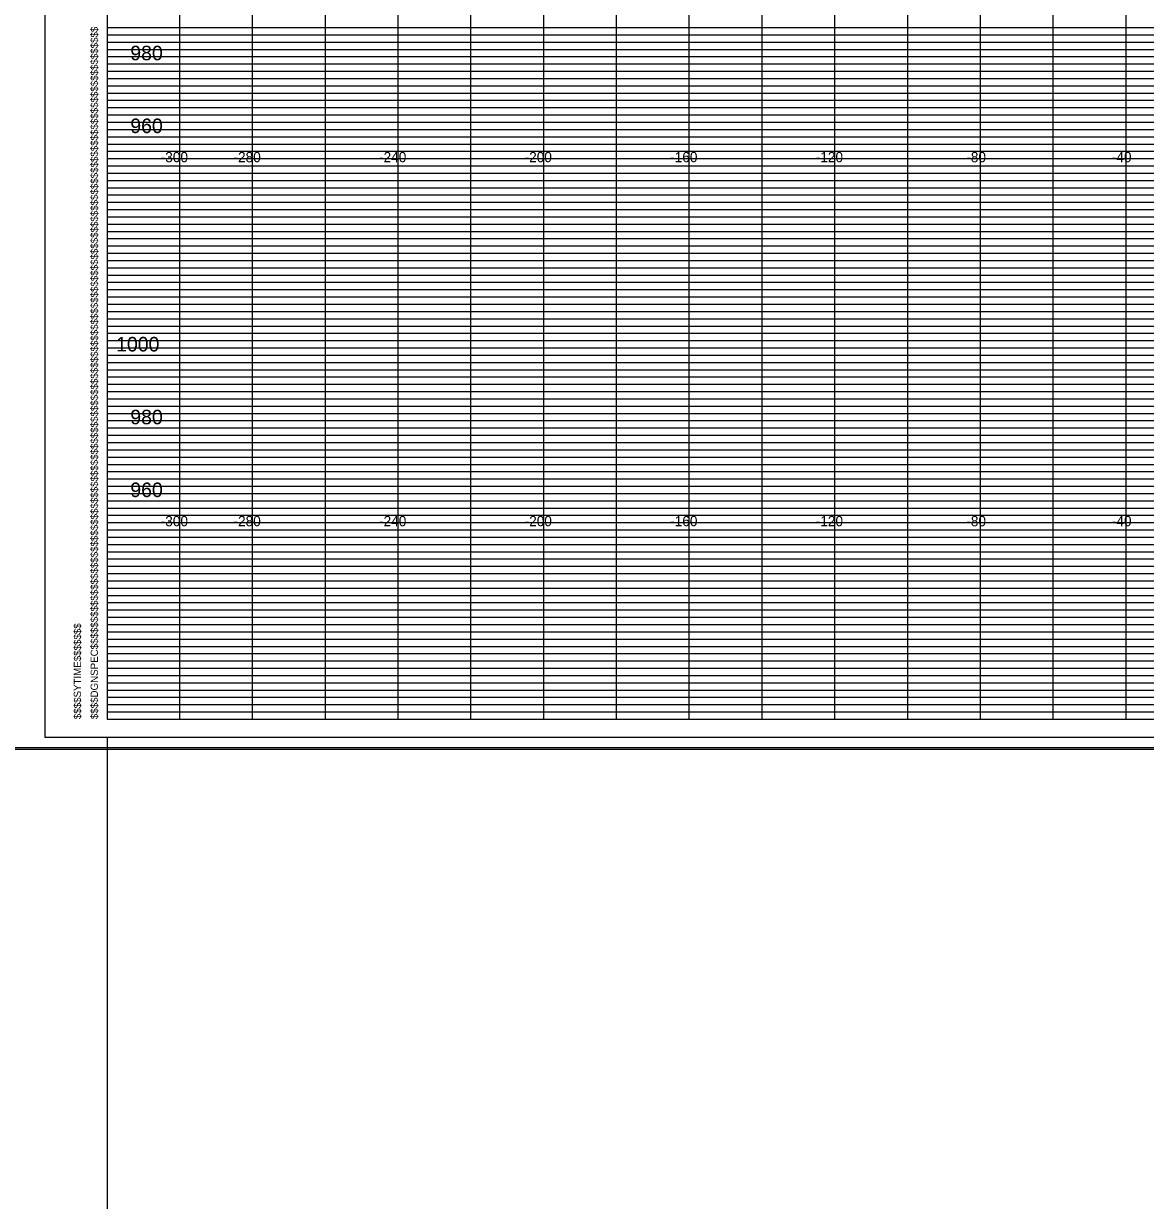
# Model space of a CAD drawing. Extents: x 2313580 to 2322968, y 282099 to 303247.
# Drawn here: x 2315275.9 to 2315584.2, y 287455.4 to 287778.8 of the extents above; entities that cross this region are included whole.
import ezdxf

# ---------------------------------------------------------------- set-up
doc = ezdxf.new("R2010")
doc.units = 0
for name, color, linetype in [('DESIGN - SCRATCH - User 1', 7, 'Continuous'), ('DESIGN - SHEET - Corner Text', 7, 'Continuous'), ('DESIGN - SHEET - Light Grid', 7, 'Continuous'), ('DESIGN - SHEET - Linework', 7, 'Continuous'), ('DESIGN - SHEET - Plot Shape', 7, 'Continuous'), ('DESIGN - TYPICAL - Text', 7, 'Continuous')]:
    doc.layers.add(name, color=color, linetype=linetype)

msp = doc.modelspace()

# ---------------------------------------------------------------- linework, layer by layer
at = {"layer": 'DESIGN - SCRATCH - User 1'}
msp.add_line((2315298.88, 287582.67), (2315298.88, 284487.81), dxfattribs=at)
at = {"layer": 'DESIGN - SHEET - Light Grid'}
for p, q in [((2315298.88, 287777.67), (2315458.88, 287777.67)), ((2315298.88, 287775.67), (2315458.88, 287775.67)), ((2315458.88, 287777.67), (2315618.88, 287777.67)), ((2315458.88, 287775.67), (2315618.88, 287775.67)), ((2315298.88, 287773.67), (2315458.88, 287773.67)), ((2315458.88, 287773.67), (2315618.88, 287773.67)), ((2315298.88, 287771.67), (2315458.88, 287771.67)), ((2315298.88, 287769.67), (2315458.88, 287769.67)), ((2315458.88, 287771.67), (2315618.88, 287771.67)), ((2315458.88, 287769.67), (2315618.88, 287769.67)), ((2315298.88, 287765.67), (2315458.88, 287765.67)), ((2315458.88, 287765.67), (2315618.88, 287765.67)), ((2315298.88, 287763.67), (2315458.88, 287763.67)), ((2315458.88, 287763.67), (2315618.88, 287763.67)), ((2315298.88, 287761.67), (2315458.88, 287761.67)), ((2315298.88, 287759.67), (2315458.88, 287759.67)), ((2315458.88, 287761.67), (2315618.88, 287761.67)), ((2315458.88, 287759.67), (2315618.88, 287759.67)), ((2315298.88, 287757.67), (2315458.88, 287757.67)), ((2315458.88, 287757.67), (2315618.88, 287757.67)), ((2315298.88, 287755.67), (2315458.88, 287755.67)), ((2315298.88, 287753.67), (2315458.88, 287753.67)), ((2315458.88, 287755.67), (2315618.88, 287755.67)), ((2315458.88, 287753.67), (2315618.88, 287753.67)), ((2315298.88, 287751.67), (2315458.88, 287751.67)), ((2315298.88, 287749.67), (2315458.88, 287749.67)), ((2315458.88, 287751.67), (2315618.88, 287751.67)), ((2315458.88, 287749.67), (2315618.88, 287749.67)), ((2315298.88, 287745.67), (2315458.88, 287745.67)), ((2315298.88, 287743.67), (2315458.88, 287743.67)), ((2315458.88, 287745.67), (2315618.88, 287745.67)), ((2315458.88, 287743.67), (2315618.88, 287743.67)), ((2315298.88, 287741.67), (2315458.88, 287741.67)), ((2315298.88, 287739.67), (2315458.88, 287739.67)), ((2315458.88, 287741.67), (2315618.88, 287741.67)), ((2315458.88, 287739.67), (2315618.88, 287739.67)), ((2315298.88, 287737.67), (2315458.88, 287737.67)), ((2315458.88, 287737.67), (2315618.88, 287737.67)), ((2315298.88, 287735.67), (2315458.88, 287735.67)), ((2315298.88, 287733.67), (2315458.88, 287733.67)), ((2315458.88, 287735.67), (2315618.88, 287735.67)), ((2315458.88, 287733.67), (2315618.88, 287733.67)), ((2315298.88, 287731.67), (2315458.88, 287731.67)), ((2315458.88, 287731.67), (2315618.88, 287731.67)), ((2315298.88, 287729.67), (2315458.88, 287729.67)), ((2315458.88, 287729.67), (2315618.88, 287729.67)), ((2315298.88, 287725.67), (2315458.88, 287725.67)), ((2315298.88, 287723.67), (2315458.88, 287723.67)), ((2315458.88, 287725.67), (2315618.88, 287725.67)), ((2315458.88, 287723.67), (2315618.88, 287723.67)), ((2315298.88, 287721.67), (2315458.88, 287721.67)), ((2315458.88, 287721.67), (2315618.88, 287721.67)), ((2315298.88, 287719.67), (2315458.88, 287719.67)), ((2315298.88, 287717.67), (2315458.88, 287717.67)), ((2315458.88, 287719.67), (2315618.88, 287719.67)), ((2315458.88, 287717.67), (2315618.88, 287717.67)), ((2315298.88, 287715.67), (2315458.88, 287715.67)), ((2315458.88, 287715.67), (2315618.88, 287715.67)), ((2315298.88, 287713.67), (2315458.88, 287713.67)), ((2315298.88, 287711.67), (2315458.88, 287711.67)), ((2315458.88, 287713.67), (2315618.88, 287713.67)), ((2315458.88, 287711.67), (2315618.88, 287711.67)), ((2315298.88, 287709.67), (2315458.88, 287709.67)), ((2315458.88, 287709.67), (2315618.88, 287709.67)), ((2315298.88, 287705.67), (2315458.88, 287705.67)), ((2315458.88, 287705.67), (2315618.88, 287705.67)), ((2315298.88, 287703.67), (2315458.88, 287703.67)), ((2315298.88, 287701.67), (2315458.88, 287701.67)), ((2315458.88, 287703.67), (2315618.88, 287703.67)), ((2315458.88, 287701.67), (2315618.88, 287701.67)), ((2315298.88, 287699.67), (2315458.88, 287699.67)), ((2315298.88, 287697.67), (2315458.88, 287697.67)), ((2315458.88, 287699.67), (2315618.88, 287699.67)), ((2315458.88, 287697.67), (2315618.88, 287697.67)), ((2315298.88, 287695.67), (2315458.88, 287695.67)), ((2315458.88, 287695.67), (2315618.88, 287695.67)), ((2315298.88, 287693.67), (2315458.88, 287693.67)), ((2315298.88, 287691.67), (2315458.88, 287691.67)), ((2315458.88, 287693.67), (2315618.88, 287693.67)), ((2315458.88, 287691.67), (2315618.88, 287691.67)), ((2315298.88, 287689.67), (2315458.88, 287689.67)), ((2315458.88, 287689.67), (2315618.88, 287689.67)), ((2315298.88, 287685.67), (2315458.88, 287685.67)), ((2315458.88, 287685.67), (2315618.88, 287685.67)), ((2315298.88, 287683.67), (2315458.88, 287683.67)), ((2315298.88, 287681.67), (2315458.88, 287681.67)), ((2315458.88, 287683.67), (2315618.88, 287683.67)), ((2315458.88, 287681.67), (2315618.88, 287681.67)), ((2315298.88, 287679.67), (2315458.88, 287679.67)), ((2315458.88, 287679.67), (2315618.88, 287679.67)), ((2315298.88, 287677.67), (2315458.88, 287677.67)), ((2315298.88, 287675.67), (2315458.88, 287675.67)), ((2315458.88, 287677.67), (2315618.88, 287677.67)), ((2315458.88, 287675.67), (2315618.88, 287675.67)), ((2315298.88, 287673.67), (2315458.88, 287673.67)), ((2315298.88, 287671.67), (2315458.88, 287671.67)), ((2315458.88, 287673.67), (2315618.88, 287673.67)), ((2315458.88, 287671.67), (2315618.88, 287671.67)), ((2315298.88, 287669.67), (2315458.88, 287669.67)), ((2315458.88, 287669.67), (2315618.88, 287669.67)), ((2315298.88, 287665.67), (2315458.88, 287665.67)), ((2315458.88, 287665.67), (2315618.88, 287665.67)), ((2315298.88, 287663.67), (2315458.88, 287663.67)), ((2315458.88, 287663.67), (2315618.88, 287663.67)), ((2315298.88, 287661.67), (2315458.88, 287661.67)), ((2315298.88, 287659.67), (2315458.88, 287659.67)), ((2315458.88, 287661.67), (2315618.88, 287661.67)), ((2315458.88, 287659.67), (2315618.88, 287659.67)), ((2315298.88, 287657.67), (2315458.88, 287657.67)), ((2315298.88, 287655.67), (2315458.88, 287655.67)), ((2315458.88, 287657.67), (2315618.88, 287657.67)), ((2315458.88, 287655.67), (2315618.88, 287655.67)), ((2315298.88, 287653.67), (2315458.88, 287653.67)), ((2315458.88, 287653.67), (2315618.88, 287653.67)), ((2315298.88, 287651.67), (2315458.88, 287651.67)), ((2315298.88, 287649.67), (2315458.88, 287649.67)), ((2315458.88, 287651.67), (2315618.88, 287651.67)), ((2315458.88, 287649.67), (2315618.88, 287649.67)), ((2315298.88, 287645.67), (2315458.88, 287645.67)), ((2315298.88, 287643.67), (2315458.88, 287643.67)), ((2315458.88, 287645.67), (2315618.88, 287645.67)), ((2315458.88, 287643.67), (2315618.88, 287643.67)), ((2315298.88, 287641.67), (2315458.88, 287641.67)), ((2315298.88, 287639.67), (2315458.88, 287639.67)), ((2315458.88, 287641.67), (2315618.88, 287641.67)), ((2315458.88, 287639.67), (2315618.88, 287639.67)), ((2315298.88, 287637.67), (2315458.88, 287637.67)), ((2315458.88, 287637.67), (2315618.88, 287637.67)), ((2315298.88, 287635.67), (2315458.88, 287635.67)), ((2315298.88, 287633.67), (2315458.88, 287633.67)), ((2315458.88, 287635.67), (2315618.88, 287635.67)), ((2315458.88, 287633.67), (2315618.88, 287633.67)), ((2315298.88, 287631.67), (2315458.88, 287631.67)), ((2315298.88, 287629.67), (2315458.88, 287629.67)), ((2315458.88, 287631.67), (2315618.88, 287631.67)), ((2315458.88, 287629.67), (2315618.88, 287629.67)), ((2315298.88, 287625.67), (2315458.88, 287625.67)), ((2315298.88, 287623.67), (2315458.88, 287623.67)), ((2315458.88, 287625.67), (2315618.88, 287625.67)), ((2315458.88, 287623.67), (2315618.88, 287623.67)), ((2315298.88, 287621.67), (2315458.88, 287621.67)), ((2315458.88, 287621.67), (2315618.88, 287621.67)), ((2315298.88, 287619.67), (2315458.88, 287619.67)), ((2315298.88, 287617.67), (2315458.88, 287617.67)), ((2315458.88, 287619.67), (2315618.88, 287619.67)), ((2315458.88, 287617.67), (2315618.88, 287617.67)), ((2315298.88, 287615.67), (2315458.88, 287615.67)), ((2315298.88, 287613.67), (2315458.88, 287613.67)), ((2315458.88, 287615.67), (2315618.88, 287615.67)), ((2315458.88, 287613.67), (2315618.88, 287613.67)), ((2315298.88, 287611.67), (2315458.88, 287611.67)), ((2315458.88, 287611.67), (2315618.88, 287611.67)), ((2315298.88, 287609.67), (2315458.88, 287609.67)), ((2315458.88, 287609.67), (2315618.88, 287609.67)), ((2315298.88, 287605.67), (2315458.88, 287605.67)), ((2315458.88, 287605.67), (2315618.88, 287605.67)), ((2315298.88, 287603.67), (2315458.88, 287603.67)), ((2315298.88, 287601.67), (2315458.88, 287601.67)), ((2315458.88, 287603.67), (2315618.88, 287603.67)), ((2315458.88, 287601.67), (2315618.88, 287601.67)), ((2315298.88, 287599.67), (2315458.88, 287599.67)), ((2315298.88, 287597.67), (2315458.88, 287597.67)), ((2315458.88, 287599.67), (2315618.88, 287599.67)), ((2315458.88, 287597.67), (2315618.88, 287597.67)), ((2315298.88, 287595.67), (2315458.88, 287595.67)), ((2315458.88, 287595.67), (2315618.88, 287595.67)), ((2315298.88, 287593.67), (2315458.88, 287593.67)), ((2315298.88, 287591.67), (2315458.88, 287591.67)), ((2315458.88, 287593.67), (2315618.88, 287593.67)), ((2315458.88, 287591.67), (2315618.88, 287591.67)), ((2315298.88, 287589.67), (2315458.88, 287589.67)), ((2315458.88, 287589.67), (2315618.88, 287589.67))]:
    msp.add_line(p, q, dxfattribs=at)
at = {"layer": 'DESIGN - SHEET - Linework'}
for p, q in [((2315318.88, 287587.67), (2315318.88, 288007.67)), ((2315338.88, 287587.67), (2315338.88, 288007.67)), ((2315358.88, 287587.67), (2315358.88, 288007.67)), ((2315378.88, 287587.67), (2315378.88, 288007.67)), ((2315398.88, 287587.67), (2315398.88, 288007.67)), ((2315418.88, 287587.67), (2315418.88, 288007.67)), ((2315438.88, 287587.67), (2315438.88, 288007.67)), ((2315458.88, 287587.67), (2315458.88, 288007.67)), ((2315478.88, 287587.67), (2315478.88, 288007.67)), ((2315498.88, 287587.67), (2315498.88, 288007.67)), ((2315518.88, 287587.67), (2315518.88, 288007.67)), ((2315538.88, 287587.67), (2315538.88, 288007.67)), ((2315558.88, 287587.67), (2315558.88, 288007.67)), ((2315578.88, 287587.67), (2315578.88, 288007.67)), ((2315298.88, 287767.67), (2315938.88, 287767.67)), ((2315298.88, 287747.67), (2315938.88, 287747.67)), ((2315298.88, 287727.67), (2315938.88, 287727.67)), ((2315298.88, 287707.67), (2315938.88, 287707.67)), ((2315298.88, 287687.67), (2315938.88, 287687.67)), ((2315298.88, 287667.67), (2315938.88, 287667.67)), ((2315298.88, 287647.67), (2315938.88, 287647.67)), ((2315298.88, 287627.67), (2315938.88, 287627.67)), ((2315298.88, 287607.67), (2315938.88, 287607.67)), ((2315262.42, 287579.39), (2315943.22, 287579.39))]:
    msp.add_line(p, q, dxfattribs=at)
msp.add_lwpolyline([(2315298.88, 288007.67), (2315298.88, 287587.67), (2315938.88, 287587.67), (2315938.88, 288007.67), (2315298.88, 288007.67)], dxfattribs=at)
at = {"layer": 'DESIGN - SHEET - Plot Shape'}
for points in [[(2315262.82, 288015.55), (2315942.82, 288015.55), (2315942.82, 287579.79), (2315262.82, 287579.79)], [(2315281.88, 288007.67), (2315938.88, 288007.67), (2315938.88, 287582.67), (2315281.88, 287582.67)]]:
    msp.add_lwpolyline(points, close=True, dxfattribs=at)

# ---------------------------------------------------------------- texts
at = {"layer": 'DESIGN - SHEET - Corner Text'}
for s, height, p in [('$$$$DGNSPEC$$$$$$$$$$$$$$$$$$$$$$$$$$$$$$$$$$$$$$$$$$$$$$$$$$$$$$$$$$$$$$$$$$$$$$$$$$$$$$$$$$$$$$$$$$$$$$$$$$$$$$$$$$$$$$$$$$$', 2.00004, (2315296.36, 287587.67)), ('$$$$SYTIME$$$$$$$', 2, (2315291.72, 287587.67))]:
    msp.add_text(s, height=height, rotation=90, dxfattribs=at).set_placement(p)
at = {"layer": 'DESIGN - SHEET - Linework'}
for p in [(2315318.88, 287747.67), (2315318.88, 287647.67)]:
    msp.add_text('-', height=0.0001, dxfattribs=at).set_placement(p)
at = {"layer": 'DESIGN - TYPICAL - Text'}
for s, height, p in [('980', 4, (2315305.26, 287768.67)), ('960', 4, (2315305.26, 287748.67)), ('-300', 2.8, (2315313.62, 287740.67)), ('-280', 2.8, (2315333.62, 287740.67)), ('-240', 2.8, (2315373.62, 287740.67)), ('-200', 2.8, (2315413.62, 287740.67)), ('-160', 2.8, (2315453.62, 287740.67)), ('-120', 2.8, (2315493.62, 287740.67)), ('-80', 2.8, (2315534.99, 287740.67)), ('-40', 2.8, (2315574.99, 287740.67)), ('1000', 4, (2315301.36, 287688.67)), ('980', 4, (2315305.26, 287668.67)), ('960', 4, (2315305.26, 287648.67)), ('-300', 2.8, (2315313.62, 287640.67)), ('-280', 2.8, (2315333.62, 287640.67)), ('-240', 2.8, (2315373.62, 287640.67)), ('-200', 2.8, (2315413.62, 287640.67)), ('-160', 2.8, (2315453.62, 287640.67)), ('-120', 2.8, (2315493.62, 287640.67)), ('-80', 2.8, (2315534.99, 287640.67)), ('-40', 2.8, (2315574.99, 287640.67))]:
    msp.add_text(s, height=height, dxfattribs=at).set_placement(p)

doc.saveas('drawing.dxf')
